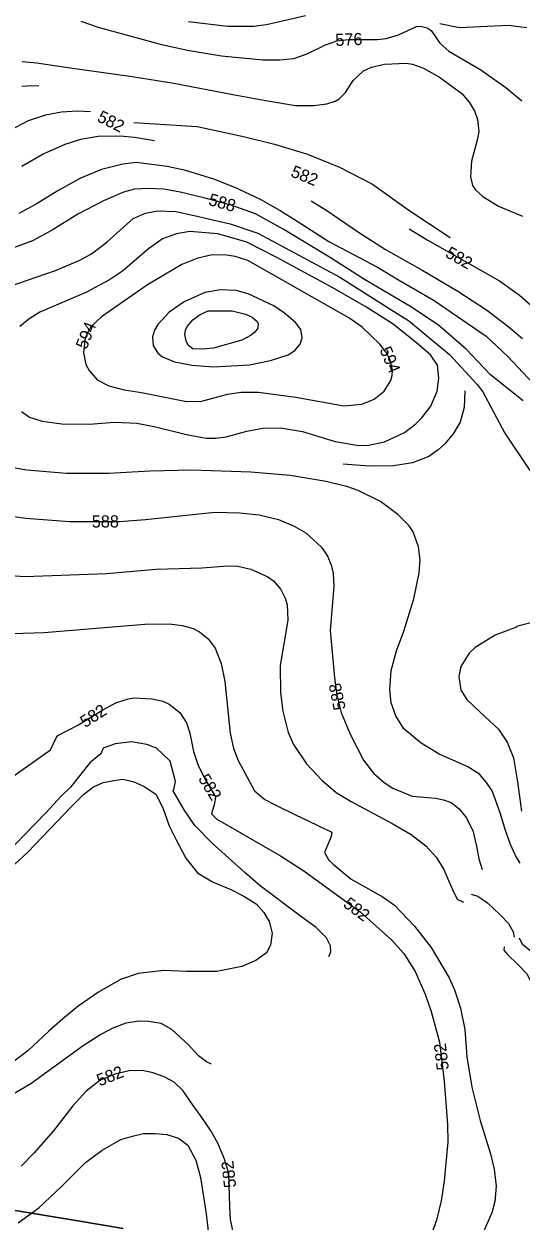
# Model space of a CAD drawing. Extents: x -709418 to -703832, y -1161719 to -1157826.
# Drawn here: x -705716 to -705388, y -1159202 to -1158413 of the extents above; entities that cross this region are included whole.
import ezdxf

# ---------------------------------------------------------------- set-up
doc = ezdxf.new("R2010")
doc.units = 0
for name, color, linetype in [('102_obvod PÚ', 7, 'Continuous'), ('103_hranice KÚ', 7, 'Continuous'), ('120_vrstevnice hlavní', 7, 'Continuous'), ('121_vrstevnice hlavní_popis', 7, 'Continuous'), ('122_vrstevnice základní', 7, 'Continuous'), ('124_vrstevnice doplňková', 7, 'Continuous'), ('206_TTP_KN', 7, 'Continuous')]:
    doc.layers.add(name, color=color, linetype=linetype)

msp = doc.modelspace()

# ---------------------------------------------------------------- linework, layer by layer
at = {"layer": '102_obvod PÚ'}
msp.add_lwpolyline([(-705732.21, -1159193.61), (-705680.34, -1159202.12), (-705650.29, -1159207.21)], dxfattribs=at)
at = {"layer": '103_hranice KÚ'}
msp.add_lwpolyline([(-705650.29, -1159207.21), (-705680.34, -1159202.12), (-705732.21, -1159193.61)], dxfattribs=at)
at = {"layer": '120_vrstevnice hlavní'}
for points in [[(-705717.11, -1158453.93), (-705710.95, -1158453.45), (-705705.97, -1158453.68)], [(-705643.34, -1158477.83), (-705626.02, -1158478.82), (-705601.54, -1158480.49), (-705570.91, -1158487.1), (-705550.56, -1158492.17), (-705528.84, -1158498.78), (-705507.81, -1158507.28), (-705486.02, -1158518.5), (-705462, -1158535.62), (-705434.65, -1158553.74)], [(-705726.92, -1158586.37), (-705694.88, -1158575.5), (-705678.86, -1158568.5), (-705671.29, -1158564.35), (-705661.13, -1158556.77), (-705643.68, -1158541.18), (-705635.68, -1158537.6), (-705627.67, -1158536.03), (-705615.65, -1158536.6), (-705603.64, -1158539.04), (-705579.86, -1158544.55), (-705561.55, -1158550.68), (-705507.42, -1158579.71), (-705469.71, -1158603.68), (-705462.27, -1158608.4), (-705435.19, -1158630.8), (-705417.01, -1158650.59)], [(-705417.01, -1158650.59), (-705413.15, -1158655.31), (-705398.7, -1158682.62), (-705382.26, -1158707.22)], [(-705388.53, -1158966.31), (-705391.67, -1158961.21), (-705395.05, -1158954.02), (-705398.42, -1158944.1), (-705401.61, -1158933.66), (-705404.81, -1158924.42), (-705407, -1158918.61), (-705410.73, -1158913.12), (-705415.5, -1158907.62), (-705423.17, -1158902.63), (-705431.52, -1158899), (-705442.08, -1158894.34), (-705453.83, -1158887.11), (-705465.35, -1158877.55), (-705470.49, -1158869.11), (-705473.64, -1158860.53), (-705474.5, -1158851.95), (-705473.64, -1158839.08), (-705470.21, -1158826.21), (-705465.35, -1158813.33), (-705458.62, -1158791.88), (-705455.19, -1158774.72), (-705454.62, -1158766.14), (-705455.62, -1158757.56), (-705459.05, -1158747.83), (-705461.77, -1158743.83), (-705469.21, -1158736.25), (-705480.65, -1158727.81), (-705495.52, -1158720.52), (-705502.96, -1158717.95), (-705517.83, -1158714.23), (-705540.14, -1158710.51), (-705566.17, -1158708.36), (-705605.07, -1158707.08), (-705632.53, -1158707.79), (-705659.99, -1158709.36), (-705687.73, -1158709.22), (-705713.76, -1158707.08), (-705736.07, -1158703.36)], [(-705514.66, -1159027.75), (-705513.38, -1159024.76), (-705513.71, -1159020.82), (-705516.25, -1159015.5), (-705523.06, -1159008.61), (-705532.62, -1159001.89), (-705560.02, -1158981.09), (-705570.05, -1158972.31), (-705591.77, -1158953.06), (-705603.03, -1158941.4), (-705610.18, -1158931.08), (-705617.4, -1158918.62), (-705616.65, -1158916.73), (-705615.8, -1158912.44), (-705619.44, -1158899.06), (-705628.43, -1158890.31), (-705634.65, -1158888.07), (-705644.92, -1158886.14), (-705655.54, -1158887.63), (-705663.44, -1158890.33), (-705665.17, -1158894.09), (-705672.22, -1158900.05), (-705678.25, -1158907.55)], [(-705678.25, -1158907.55), (-705684.97, -1158916.08), (-705691.17, -1158922.05), (-705701.22, -1158933), (-705728.84, -1158961.42)], [(-705592.02, -1159098.89), (-705595.32, -1159097.37), (-705600.61, -1159093.4), (-705607.59, -1159085.83), (-705618.16, -1159075.84), (-705625.34, -1159072.04), (-705633.55, -1159070.63), (-705639.71, -1159070.43), (-705648.68, -1159071.73), (-705657.26, -1159075.11), (-705665.03, -1159079.16), (-705676.79, -1159086.74), (-705696.73, -1159101.2), (-705711.17, -1159111.74), (-705726.63, -1159120.74)]]:
    msp.add_lwpolyline(points, dxfattribs=at)
at = {"layer": '122_vrstevnice základní'}
for points in [[(-705678.29, -1158411.04), (-705666.85, -1158414.9), (-705625.95, -1158426.2), (-705607.93, -1158430.2), (-705585.62, -1158433.78), (-705558.16, -1158436.5), (-705547.01, -1158436.5), (-705537.85, -1158435.49), (-705529.13, -1158432.49), (-705516.97, -1158426.48), (-705509.54, -1158424.05), (-705501.82, -1158423.05), (-705482.94, -1158423.05), (-705476.93, -1158422.48), (-705468.92, -1158420.05), (-705456.91, -1158414.47), (-705454.33, -1158414.19), (-705449.9, -1158415.33), (-705447.33, -1158417.19), (-705441.61, -1158425.48), (-705435.74, -1158430.78), (-705414.43, -1158443.07), (-705397.99, -1158454.66), (-705387.55, -1158463.53)], [(-705530.13, -1158407.46), (-705555.87, -1158413.33), (-705564.46, -1158414.47), (-705581.62, -1158414.47), (-705607.36, -1158411.47)], [(-705384.26, -1158415.33), (-705396.27, -1158413.9), (-705428.59, -1158415.33), (-705441.46, -1158412.76)], [(-705717.03, -1158437.55), (-705707.26, -1158438.46), (-705688.28, -1158441.29), (-705644.44, -1158447.46), (-705616.87, -1158451.88), (-705578.13, -1158459.27), (-705556.39, -1158463.32), (-705536.7, -1158466.67), (-705524.7, -1158466.53), (-705516.12, -1158465.53), (-705510.54, -1158463.67), (-705507.96, -1158462.09), (-705503.82, -1158457.95), (-705498.67, -1158450.08), (-705491.95, -1158443.79), (-705486.66, -1158441.22), (-705478.08, -1158439.35), (-705463.77, -1158438.64), (-705459.48, -1158439.35), (-705452.33, -1158441.93), (-705441.89, -1158447.94), (-705427.16, -1158458.66), (-705422.16, -1158464.38), (-705418.72, -1158470.1), (-705416.72, -1158475.82), (-705415.86, -1158483.83), (-705416.86, -1158489.55), (-705420.73, -1158503.28), (-705421.44, -1158513.58), (-705420.01, -1158519.3), (-705418.01, -1158522.16), (-705413.29, -1158526.59), (-705402.85, -1158533.03), (-705387.12, -1158539.61)], [(-705671.85, -1158470.68), (-705680.47, -1158470.25), (-705691.09, -1158470.88), (-705701.54, -1158473.06), (-705713.01, -1158476.74), (-705721.76, -1158481.32)], [(-705629.76, -1158489.86), (-705642.83, -1158487.79), (-705652.41, -1158486.71), (-705666.78, -1158486.99), (-705678.42, -1158488.98), (-705688.7, -1158492.35), (-705702.98, -1158498.76), (-705717.05, -1158506.9)], [(-705574.04, -1158521.74), (-705589.81, -1158515.41), (-705608.94, -1158509.5), (-705621.23, -1158506.71), (-705641.69, -1158504.24), (-705650.59, -1158505.22), (-705664.63, -1158508.74), (-705679.02, -1158514.82), (-705693.94, -1158523.13), (-705707.75, -1158531.6), (-705719.2, -1158537.75)], [(-705386.69, -1158661.31), (-705408.14, -1158644.15), (-705424.3, -1158627.28), (-705442.32, -1158611.69), (-705460.34, -1158599.67), (-705491.23, -1158581.37), (-705514.4, -1158566.64), (-705544.93, -1158548.13), (-705563.17, -1158538.13), (-705579.89, -1158532.14), (-705597.13, -1158527.44), (-705612.66, -1158523.78), (-705623.59, -1158521.67), (-705633.6, -1158521.4), (-705642.83, -1158521.87), (-705650.19, -1158523.71), (-705663.38, -1158529.46), (-705680.3, -1158538.18), (-705697.17, -1158548.9), (-705710.04, -1158555.91), (-705734.64, -1158564.78)], [(-705574.04, -1158521.74), (-705560.05, -1158528.31), (-705546.92, -1158535.73), (-705535.6, -1158542.94), (-705514.8, -1158556.21), (-705482.74, -1158573.13), (-705468.73, -1158581.45), (-705445.38, -1158595.08), (-705411, -1158618.69), (-705396.84, -1158632.14), (-705383.26, -1158646.44), (-705369.53, -1158659.02), (-705344.64, -1158677.33)], [(-705526.47, -1158529.46), (-705516.16, -1158535.78), (-705495.19, -1158550.08), (-705477.28, -1158561.46), (-705452.88, -1158575.34), (-705429.68, -1158588.98), (-705410.83, -1158601.29), (-705396.68, -1158612.14), (-705386.97, -1158620.23)], [(-705461.78, -1158547.99), (-705449.82, -1158555.07), (-705402.25, -1158582.31), (-705388.94, -1158591.62), (-705378.03, -1158601.26), (-705365.41, -1158615.26), (-705349.59, -1158634.34), (-705339.37, -1158645), (-705329.99, -1158651.73), (-705318.52, -1158657.68), (-705308.78, -1158659.95), (-705294.58, -1158661.9), (-705282.09, -1158663.16)], [(-705443.32, -1158654.88), (-705442.18, -1158646.3), (-705443.18, -1158637.86), (-705447.72, -1158630.99), (-705456.71, -1158623.43), (-705472.41, -1158610.73), (-705490.43, -1158599.47), (-705512.18, -1158586.89), (-705548.96, -1158566.87), (-705568.84, -1158556.68), (-705588.02, -1158551.31), (-705606.36, -1158549.76), (-705615.08, -1158551.19), (-705624.38, -1158554.62), (-705633.67, -1158561.2), (-705650.84, -1158575.93), (-705659.42, -1158581.65), (-705674.86, -1158589.95), (-705705.18, -1158602.82), (-705712.62, -1158607.4), (-705718.48, -1158612.4)], [(-705481.08, -1158623.99), (-705492.81, -1158612.83), (-705501.67, -1158606.68), (-705568.17, -1158568.83), (-705576.61, -1158566.21), (-705583.62, -1158565.06), (-705592.77, -1158565.21), (-705601.78, -1158567.5), (-705611.65, -1158571.5), (-705634.24, -1158584.94), (-705664.71, -1158605.97), (-705671.86, -1158612.83), (-705675.43, -1158619.7), (-705676.58, -1158629.42), (-705675, -1158637.43), (-705672.86, -1158641.43), (-705667.42, -1158647.44), (-705659.7, -1158651.44), (-705649.69, -1158654.16), (-705638.25, -1158655.88), (-705609.65, -1158661.6), (-705599.35, -1158661.74), (-705581.62, -1158656.88), (-705572.46, -1158655.59), (-705561.02, -1158655.59), (-705536.42, -1158658.88), (-705504.96, -1158664.75), (-705492.95, -1158663.46), (-705484.94, -1158660.17), (-705478.22, -1158654.88), (-705473.93, -1158648.01), (-705472.93, -1158644.58), (-705472.78, -1158641.15), (-705474.36, -1158634.28), (-705477.22, -1158629.13), (-705481.08, -1158623.99)], [(-705544, -1158603.54), (-705551.01, -1158598.81), (-705567.89, -1158590.81), (-705575.9, -1158588.66), (-705586.19, -1158588.09), (-705596.49, -1158589.95), (-705610.22, -1158596.1), (-705620.09, -1158602.82), (-705627.52, -1158610.97), (-705629.67, -1158614.83), (-705630.96, -1158619.12), (-705630.67, -1158624.84), (-705627.52, -1158629.99), (-705624.38, -1158632.42), (-705616.51, -1158635.57), (-705605.07, -1158637.86), (-705590.77, -1158639), (-705567.03, -1158637.57), (-705553.3, -1158634.85), (-705541.57, -1158630.99), (-705537.14, -1158628.13), (-705533.56, -1158623.99), (-705532.28, -1158619.7), (-705533.28, -1158614.4), (-705536.71, -1158609.69), (-705544, -1158603.54)], [(-705717.34, -1158668.46), (-705712.19, -1158672.18), (-705703.75, -1158674.76), (-705690.88, -1158676.47), (-705672.86, -1158676.76), (-705655.98, -1158675.33), (-705641.4, -1158676.04), (-705629.96, -1158678.19), (-705608.5, -1158683.62), (-705595.63, -1158685.91), (-705589.34, -1158686.05), (-705582.47, -1158685.2), (-705568.74, -1158681.33), (-705558.45, -1158679.33), (-705546.72, -1158679.05), (-705532.13, -1158681.48), (-705510.68, -1158688.2), (-705494.95, -1158690.77), (-705488.37, -1158690.49), (-705478.08, -1158688.49), (-705464.77, -1158682.33), (-705457.48, -1158676.61), (-705453.33, -1158672.47), (-705447.61, -1158664.89), (-705443.32, -1158654.88)], [(-705737.79, -1158735.54), (-705714.62, -1158738.83), (-705685.73, -1158740.83), (-705652.84, -1158740.83), (-705635.68, -1158739.68), (-705589.91, -1158734.82), (-705573.61, -1158735.25), (-705560.74, -1158736.54), (-705547.86, -1158739.68), (-705537.57, -1158743.97), (-705529.85, -1158748.41), (-705519.69, -1158757.85), (-705515.54, -1158763.85), (-705513.26, -1158769.57), (-705511.97, -1158775.29), (-705511.54, -1158783.88), (-705513.83, -1158812.76), (-705511.11, -1158843.94), (-705509.4, -1158855.38), (-705506.68, -1158866.82), (-705500.67, -1158881.12), (-705491.8, -1158898.29), (-705485.22, -1158906.87), (-705478.36, -1158913.02), (-705472.64, -1158916.74), (-705459.77, -1158922.17), (-705444.32, -1158923.46), (-705439.18, -1158924.46), (-705434.03, -1158926.32), (-705428.88, -1158930.32), (-705424.3, -1158936.04), (-705419.72, -1158944.62), (-705417.44, -1158955.08), (-705415.95, -1158963.46), (-705413.63, -1158970.35)], [(-705733.93, -1158775.87), (-705715.14, -1158777.3), (-705661.42, -1158775.15), (-705628.53, -1158772.29), (-705598.49, -1158771.43), (-705581.33, -1158770.15), (-705574.75, -1158770.43), (-705566.17, -1158772.43), (-705555.02, -1158777.44), (-705551.3, -1158780.16), (-705546.44, -1158785.88), (-705543.29, -1158791.88), (-705542.15, -1158795.89), (-705541.86, -1158805.9), (-705546.86, -1158835.93), (-705546.58, -1158853.95), (-705545.15, -1158865.97), (-705541.57, -1158879.98), (-705538.14, -1158887.99), (-705529.47, -1158900.73), (-705519.27, -1158911.55), (-705509.9, -1158919.63), (-705500.01, -1158925.5), (-705472.58, -1158940.27), (-705460.47, -1158947.34), (-705450.76, -1158954.91), (-705443.96, -1158962.29), (-705438.87, -1158970.36), (-705435.66, -1158978.07), (-705433.29, -1158983.72), (-705430.08, -1158990.06), (-705426.02, -1158992.06)], [(-705730.35, -1158815.05), (-705702.32, -1158814.19), (-705635.96, -1158808.62), (-705619.94, -1158808.47), (-705611.36, -1158809.47), (-705604.21, -1158811.48), (-705599.92, -1158813.77), (-705594.35, -1158818.34), (-705589.77, -1158824.49), (-705585.76, -1158834.5), (-705583.33, -1158846.52), (-705579.9, -1158880.55), (-705577.61, -1158890.56), (-705574.47, -1158898.57), (-705563.74, -1158918.45), (-705556.95, -1158924.16), (-705550.1, -1158927.68), (-705537.11, -1158934.25), (-705512.87, -1158945.85), (-705513.15, -1158948.57), (-705517.56, -1158959.25), (-705514.71, -1158964.2), (-705511.97, -1158966.83), (-705499.96, -1158976.8), (-705479.51, -1158988.24), (-705471.5, -1158993.96), (-705458.2, -1159007.83), (-705447.33, -1159021.85), (-705435.46, -1159041.87), (-705431.88, -1159049.88), (-705427.88, -1159061.89), (-705425.16, -1159075.91), (-705423.87, -1159093.93), (-705420.44, -1159113.95), (-705415.01, -1159135.97), (-705408.14, -1159158), (-705405.85, -1159168.01), (-705404.34, -1159179.18), (-705405.25, -1159189.44), (-705407.34, -1159196.79), (-705413.91, -1159211.81)], [(-705663.71, -1158865.11), (-705655.12, -1158860.53), (-705647.12, -1158857.81), (-705643.11, -1158857.24), (-705631.39, -1158857.81), (-705624.23, -1158859.39), (-705619.94, -1158861.39), (-705612.94, -1158866.97), (-705608.5, -1158873.69), (-705606.36, -1158880.55), (-705604.07, -1158892.56), (-705601.21, -1158901.15), (-705596.63, -1158910.3), (-705589.48, -1158922.46), (-705590.05, -1158926.89), (-705592.06, -1158933.75), (-705588.34, -1158937.47), (-705585.05, -1158939.19), (-705546.72, -1158961.35), (-705531.28, -1158971.22), (-705494.09, -1158998.4), (-705473.35, -1159016.84), (-705465.2, -1159025.85), (-705457.77, -1159037.72), (-705451.33, -1159052.74), (-705447.33, -1159064.18), (-705441.89, -1159084.2), (-705438.75, -1159109.95), (-705436.46, -1159138.55), (-705436.32, -1159149.99), (-705438.75, -1159176.02), (-705440.75, -1159188.89), (-705443.75, -1159201.76), (-705457.62, -1159240.37)], [(-705728.35, -1158912.73), (-705698.17, -1158891.42), (-705694.6, -1158883.56), (-705693.31, -1158881.98), (-705679.72, -1158875.12), (-705663.71, -1158865.11)], [(-705727.54, -1158972.1), (-705713.25, -1158959.07), (-705684.46, -1158928.98), (-705676.36, -1158920.8), (-705670, -1158915.86), (-705663.47, -1158912.98), (-705656.44, -1158911.64), (-705650.78, -1158910.81), (-705643.76, -1158912.44), (-705636.58, -1158915.73), (-705628.9, -1158920.74), (-705624.14, -1158929.67), (-705620.09, -1158941.52), (-705615.51, -1158950.97), (-705609.12, -1158962.89), (-705601.29, -1158972.53), (-705591.55, -1158978.57), (-705579.41, -1158983.6), (-705570.69, -1158988.1), (-705562.66, -1158993.11), (-705557.55, -1158998.79), (-705553.98, -1159004.64), (-705552.13, -1159012.36), (-705553.2, -1159020.41), (-705555.8, -1159025.36), (-705562.82, -1159030.35), (-705572.1, -1159034.41), (-705588.56, -1159037.59), (-705608.37, -1159037.69), (-705623.45, -1159037.1), (-705640.35, -1159038.92), (-705652.02, -1159042.98), (-705666.63, -1159051.3), (-705680.04, -1159060.49), (-705690.19, -1159068.84), (-705699.31, -1159077.02), (-705713.29, -1159090.01), (-705723, -1159097.43)], [(-705420.83, -1158986.75), (-705416.49, -1158988.06), (-705410.19, -1158992.36), (-705401.85, -1159000.27), (-705396.4, -1159005.94), (-705393.18, -1159011.43), (-705392.54, -1159014.96)], [(-705399.19, -1159021.43), (-705399.45, -1159023.56), (-705397.07, -1159026.31), (-705389.92, -1159033.36), (-705384.3, -1159039.2), (-705380.21, -1159046.79), (-705381.27, -1159053.11), (-705380.82, -1159065.09), (-705377.31, -1159082.55), (-705376.13, -1159092.46), (-705371.53, -1159104.8), (-705368.38, -1159113.95), (-705364.09, -1159120.81), (-705355.37, -1159132.26), (-705351.22, -1159139.12), (-705348.08, -1159145.99), (-705345.79, -1159157.43), (-705346.65, -1159173.44), (-705347.93, -1159178.02), (-705351.08, -1159184.89), (-705355.66, -1159192.18)], [(-705264.09, -1159159.04), (-705265.41, -1159151.71), (-705269.42, -1159142.55), (-705278.14, -1159133.11), (-705286.15, -1159126.96), (-705302.17, -1159116.67), (-705321.9, -1159100.65), (-705327.91, -1159093.93), (-705332.2, -1159087.06), (-705342.03, -1159065.65), (-705344.21, -1159057.1), (-705345.71, -1159048.38), (-705355.12, -1159040.54), (-705366.2, -1159035.02), (-705378.63, -1159026.75), (-705386.97, -1159019.87), (-705388.98, -1159015.73)], [(-705604.68, -1159125.34), (-705611.11, -1159116.21), (-705616.73, -1159110.71), (-705622.88, -1159107.43), (-705630.57, -1159104.48), (-705637.75, -1159103.07), (-705646.31, -1159103.2), (-705655.74, -1159105.38), (-705665.66, -1159109.68), (-705674.77, -1159116.66), (-705683.55, -1159126.37), (-705696.25, -1159142.72), (-705709.16, -1159157.55), (-705717.59, -1159166.06)], [(-705580.77, -1159171), (-705583.46, -1159161.4), (-705587.86, -1159150.93), (-705592.78, -1159142.35), (-705598.9, -1159133.42), (-705604.68, -1159125.34)], [(-705719.49, -1159203.45), (-705705.95, -1159193.52), (-705691, -1159179.4), (-705675.18, -1159163.74), (-705664.19, -1159155.41), (-705651.93, -1159148.4), (-705644.22, -1159146.22), (-705636.86, -1159144.54), (-705629.16, -1159144.58), (-705621.63, -1159145.13), (-705613.95, -1159147.56), (-705607.81, -1159152.22), (-705602.38, -1159162.17), (-705599.36, -1159173.47), (-705595.59, -1159197.61), (-705594.12, -1159210.8), (-705591.96, -1159223.98), (-705586.39, -1159244.68), (-705580.31, -1159259.94), (-705574.38, -1159271.78), (-705565.22, -1159287.56), (-705543.49, -1159312.11), (-705531.39, -1159321.07), (-705519.61, -1159327.63)], [(-705574.75, -1159224.07), (-705579.47, -1159201.19), (-705580.04, -1159192.61), (-705580.77, -1159171)]]:
    msp.add_lwpolyline(points, dxfattribs=at)
at = {"layer": '124_vrstevnice doplňková'}
for points in [[(-705609.22, -1158614.83), (-705608.07, -1158612.4), (-705604.5, -1158607.97), (-705599.64, -1158604.39), (-705594.34, -1158602.1), (-705578.54, -1158601.97), (-705569.6, -1158604.25), (-705565.31, -1158606.25), (-705562.02, -1158608.97), (-705561.31, -1158610.54), (-705561.57, -1158613.47), (-705563.45, -1158616.12), (-705565.88, -1158618.12), (-705572.03, -1158621.41), (-705590.77, -1158626.7), (-705597.63, -1158627.28), (-705604.5, -1158626.99), (-705607.36, -1158624.84), (-705608.79, -1158621.98), (-705609.65, -1158617.69), (-705609.22, -1158614.83)], [(-705425.16, -1158654.73), (-705425.45, -1158665.75), (-705428.16, -1158675.33), (-705432.88, -1158683.19), (-705438.17, -1158689.63), (-705442.56, -1158693.62), (-705448.93, -1158698.14), (-705459.69, -1158702.26), (-705472.07, -1158704.22), (-705488.09, -1158704.5), (-705505.39, -1158703.22)], [(-705249.4, -1158768.14), (-705260.55, -1158771.15), (-705277.28, -1158780.3), (-705292.16, -1158786.74), (-705324.91, -1158797.03), (-705350.36, -1158802.18), (-705376.53, -1158806.33), (-705391.01, -1158810.18), (-705390.98, -1158810.62), (-705405.14, -1158815.91), (-705418.29, -1158823.92), (-705422.3, -1158827.78), (-705427.73, -1158836.65), (-705429.02, -1158843.08), (-705427.62, -1158852.19), (-705423.72, -1158858.36), (-705414.88, -1158866.6), (-705402.81, -1158877.93), (-705397.27, -1158886.38), (-705393.05, -1158896.81), (-705390.4, -1158912.54), (-705387.76, -1158932.02)]]:
    msp.add_lwpolyline(points, dxfattribs=at)
at = {"layer": '206_TTP_KN'}
for p, q in [((-705732.21, -1159193.61), (-705680.34, -1159202.12)), ((-705680.34, -1159202.12), (-705650.29, -1159207.21))]:
    msp.add_line(p, q, dxfattribs=at)

# ---------------------------------------------------------------- texts
at = {"layer": '121_vrstevnice hlavní_popis'}
for s, rotation, p in [('576', 2.19155, (-705510.3, -1158427.33)), ('582', 333.29031, (-705668.09, -1158476.63)), ('582', 337.77463, (-705540.47, -1158513.15)), ('588', 344.44209, (-705594.67, -1158532.07)), ('582', 330.33462, (-705438.53, -1158566.06)), ('594', 68.20964, (-705674.52, -1158627.91)), ('594', 292.83289, (-705481.47, -1158627.56)), ('588', 0.24154, (-705670.99, -1158744.91)), ('588', 101.47747, (-705503.54, -1158864.43)), ('582', 32.50082, (-705675.47, -1158877.22)), ('582', 301.86899, (-705601.19, -1158910.56)), ('582', 323.13938, (-705505.87, -1158994.46)), ('582', 96.85183, (-705435.56, -1159102.3)), ('582', 21.72527, (-705665.86, -1159113.56)), ('582', 96.41882, (-705575.8, -1159179.88))]:
    msp.add_text(s, height=8, rotation=rotation, dxfattribs=at).set_placement(p)

doc.saveas('drawing.dxf')
